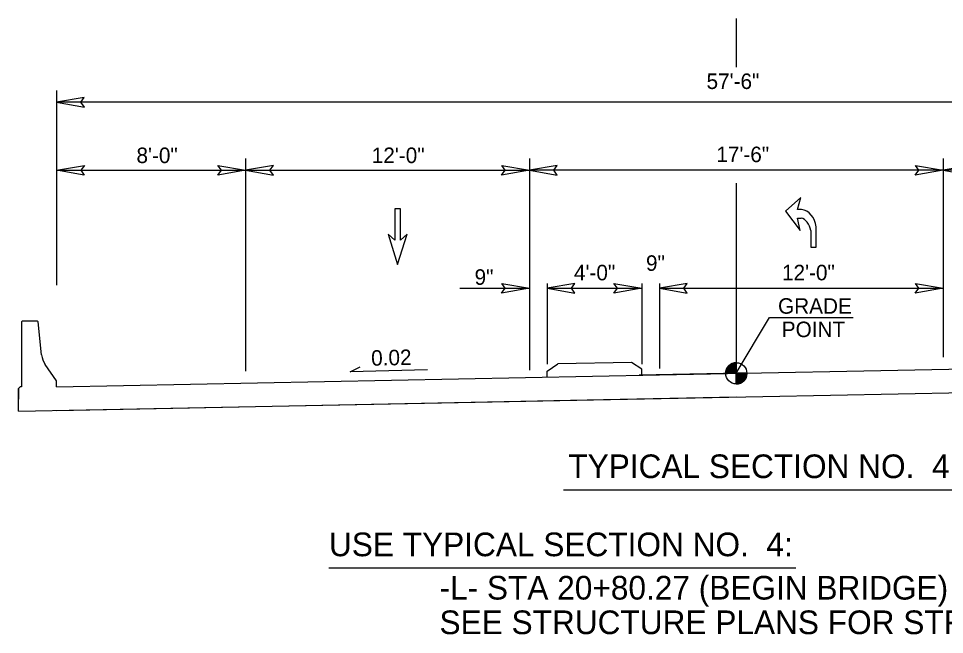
# Model space of a CAD drawing. Extents: x 1901582 to 1902252, y 193723 to 194156.
# Drawn here: x 1902016.27 to 1902055.44, y 193977.78 to 194003.82 of the extents above; entities that cross this region are included whole.
import ezdxf

# ---------------------------------------------------------------- set-up
doc = ezdxf.new("R2010")
doc.units = 0
for name, color, linetype in [('MARK BIKE LEFT ARROW CELL', 7, 'Continuous'), ('Old_Level_1', 7, 'Continuous'), ('Old_Level_11', 7, 'Continuous'), ('Old_Level_2', 7, 'Continuous'), ('Prop Dimension', 7, 'Continuous'), ('Prop Dimension Text', 7, 'Continuous'), ('Typical Grade Point Symbol CELL', 7, 'Continuous'), ('Typical Pavement Slope Information CELL', 7, 'Continuous'), ('Typical Terminator CELL', 7, 'Continuous'), ('Typical Text Grade Point CELL', 7, 'Continuous')]:
    doc.layers.add(name, color=color, linetype=linetype)

msp = doc.modelspace()

# ---------------------------------------------------------------- linework, layer by layer
at = {"layer": 'MARK BIKE LEFT ARROW CELL'}
for p, q in [((1902049.368, 193996.257), (1902048.718, 193995.672)), ((1902049.368, 193996.257), (1902048.718, 193995.672)), ((1902049.217, 193995.749), (1902049.368, 193996.257)), ((1902049.217, 193995.749), (1902049.368, 193996.257)), ((1902049.391, 193995.749), (1902049.217, 193995.749)), ((1902049.391, 193995.749), (1902049.217, 193995.749)), ((1902048.718, 193995.672), (1902049.333, 193994.864)), ((1902048.718, 193995.672), (1902049.333, 193994.864)), ((1902049.333, 193994.864), (1902049.217, 193995.383)), ((1902049.217, 193995.383), (1902049.372, 193995.383)), ((1902049.333, 193994.864), (1902049.217, 193995.383)), ((1902049.217, 193995.383), (1902049.372, 193995.383)), ((1902050.013, 193994.157), (1902050.013, 193995.018)), ((1902050.013, 193994.157), (1902050.013, 193995.018)), ((1902049.782, 193994.864), (1902049.782, 193994.157)), ((1902049.782, 193994.864), (1902049.782, 193994.157)), ((1902049.782, 193994.157), (1902050.013, 193994.157)), ((1902049.782, 193994.157), (1902050.013, 193994.157))]:
    msp.add_line(p, q, dxfattribs=at)
for centre, major_axis, ratio in [((1902049.455, 193995.082), (-0.294, 0.632), 0.75825), ((1902049.455, 193995.082), (-0.294, 0.632), 0.75825), ((1902049.436, 193994.928), (-0.204, 0.44), 0.652763), ((1902049.436, 193994.928), (-0.204, 0.44), 0.652763)]:
    msp.add_ellipse(centre, major_axis=major_axis, ratio=ratio, start_param=4.277405, end_param=5.848201, dxfattribs=at)
at = {"layer": 'Old_Level_1'}
for p, q in [((1902017.881, 194000.779), (1902017.881, 193992.543)), ((1902025.881, 193997.904), (1902025.881, 193988.912)), ((1902037.881, 193997.904), (1902037.881, 193988.95)), ((1902055.381, 193997.904), (1902055.381, 193989.501)), ((1902038.631, 193992.619), (1902038.631, 193989.203)), ((1902042.631, 193992.619), (1902042.631, 193989.203)), ((1902043.381, 193992.619), (1902043.381, 193989.025)), ((1902016.437, 193991.029), (1902016.404, 193990.996)), ((1902016.404, 193990.996), (1902016.404, 193988.248)), ((1902017.067, 193991.029), (1902016.437, 193991.029)), ((1902017.103, 193990.992), (1902017.067, 193991.029)), ((1902017.25, 193989.601), (1902017.103, 193990.992)), ((1902017.881, 193988.509), (1902017.402, 193989.194)), ((1902038.631, 193988.917), (1902039.089, 193989.218)), ((1902042.2, 193989.28), (1902039.089, 193989.218)), ((1902042.631, 193988.997), (1902042.2, 193989.28)), ((1902043.381, 193988.758), (1902075.381, 193989.398)), ((1902017.881, 193988.248), (1902043.381, 193988.758)), ((1902038.631, 193988.663), (1902038.631, 193988.917)), ((1902046.81, 193988.827), (1902042.523, 193988.741)), ((1902042.631, 193988.743), (1902042.631, 193988.997)), ((1902016.274, 193987.216), (1902076.989, 193988.43)), ((1902017.881, 193988.248), (1902017.881, 193988.509)), ((1902016.339, 193988.248), (1902016.274, 193988.183)), ((1902016.274, 193987.216), (1902016.274, 193988.183)), ((1902016.274, 193988.183), (1902016.274, 193987.726)), ((1902016.404, 193988.248), (1902016.339, 193988.248)), ((1902017.901, 193987.248), (1902046.631, 193987.823))]:
    msp.add_line(p, q, dxfattribs=at)
msp.add_arc((1902018.114, 193989.692), 0.869, 186.0111, 214.9913, dxfattribs=at)
at = {"layer": 'Old_Level_11'}
for p, q in [((1902046.631, 194003.817), (1902046.631, 194001.764)), ((1902046.631, 193996.855), (1902046.631, 193988.823)), ((1902039.318, 193983.898), (1902055.943, 193983.898)), ((1902029.404, 193980.597), (1902049.147, 193980.597))]:
    msp.add_line(p, q, dxfattribs=at)
at = {"layer": 'Prop Dimension'}
msp.add_lwpolyline([(1902032.705, 193994.696), (1902032.434, 193994.446), (1902032.434, 193995.779), (1902032.184, 193995.779), (1902032.184, 193994.446), (1902031.913, 193994.696), (1902032.309, 193993.425)], close=True, dxfattribs=at)
msp.add_lwpolyline([(1902032.705, 193994.696), (1902032.434, 193994.446), (1902032.434, 193995.779), (1902032.184, 193995.779), (1902032.184, 193994.446), (1902031.913, 193994.696), (1902032.309, 193993.425)], close=True, dxfattribs=at)
at = {"layer": 'Prop Dimension Text'}
for p, q in [((1902075.381, 194000.279), (1902017.881, 194000.279)), ((1902017.881, 193997.404), (1902025.881, 193997.404)), ((1902025.881, 193997.404), (1902037.881, 193997.404)), ((1902026.631, 193997.404), (1902037.631, 193997.404)), ((1902055.381, 193997.404), (1902037.881, 193997.404)), ((1902067.381, 193997.404), (1902055.381, 193997.404)), ((1902034.935, 193992.417), (1902037.881, 193992.417)), ((1902034.978, 193992.417), (1902037.881, 193992.417)), ((1902038.631, 193992.417), (1902042.631, 193992.417)), ((1902043.381, 193992.417), (1902055.381, 193992.417))]:
    msp.add_line(p, q, dxfattribs=at)
at = {"layer": 'Typical Grade Point Symbol CELL'}
for p, q in [((1902046.631, 193988.823), (1902046.631, 193989.271)), ((1902046.184, 193988.823), (1902046.631, 193988.823)), ((1902046.632, 193988.375), (1902046.631, 193988.823)), ((1902047.079, 193988.823), (1902046.631, 193988.823)), ((1902046.631, 193988.823), (1902046.632, 193988.375))]:
    msp.add_line(p, q, dxfattribs=at)
for points in [[(1902046.269, 193989.086), (1902046.269, 193988.823)], [(1902046.278, 193989.098), (1902046.278, 193988.823)], [(1902046.287, 193989.108), (1902046.287, 193988.823)], [(1902046.296, 193989.119), (1902046.296, 193988.823)], [(1902046.305, 193989.129), (1902046.305, 193988.823)], [(1902046.314, 193989.138), (1902046.314, 193988.823)], [(1902046.323, 193989.147), (1902046.323, 193988.823)], [(1902046.332, 193989.155), (1902046.332, 193988.823)], [(1902046.341, 193989.163), (1902046.341, 193988.823)], [(1902046.35, 193989.171), (1902046.35, 193988.823)], [(1902046.359, 193989.178), (1902046.359, 193988.823)], [(1902046.368, 193989.184), (1902046.368, 193988.823)], [(1902046.377, 193989.191), (1902046.377, 193988.823)], [(1902046.386, 193989.197), (1902046.386, 193988.823)], [(1902046.395, 193989.203), (1902046.395, 193988.823)], [(1902046.404, 193989.208), (1902046.404, 193988.823)], [(1902046.412, 193989.213), (1902046.412, 193988.823)], [(1902046.421, 193989.218), (1902046.421, 193988.823)], [(1902046.43, 193989.223), (1902046.43, 193988.823)], [(1902046.439, 193989.227), (1902046.439, 193988.823)], [(1902046.448, 193989.231), (1902046.448, 193988.823)], [(1902046.457, 193989.235), (1902046.457, 193988.823)], [(1902046.466, 193989.239), (1902046.466, 193988.823)], [(1902046.475, 193989.243), (1902046.475, 193988.823)], [(1902046.484, 193989.246), (1902046.484, 193988.823)], [(1902046.493, 193989.249), (1902046.493, 193988.823)], [(1902046.502, 193989.252), (1902046.502, 193988.823)], [(1902046.511, 193989.254), (1902046.511, 193988.823)], [(1902046.52, 193989.257), (1902046.52, 193988.823)], [(1902046.529, 193989.259), (1902046.529, 193988.823)], [(1902046.538, 193989.261), (1902046.538, 193988.823)], [(1902046.547, 193989.263), (1902046.547, 193988.823)], [(1902046.556, 193989.265), (1902046.556, 193988.823)], [(1902046.565, 193989.266), (1902046.565, 193988.823)], [(1902046.574, 193989.267), (1902046.574, 193988.823)], [(1902046.583, 193989.268), (1902046.583, 193988.823)], [(1902046.592, 193989.269), (1902046.592, 193988.823)], [(1902046.6, 193989.27), (1902046.6, 193988.823)], [(1902046.609, 193989.27), (1902046.609, 193988.823)], [(1902046.618, 193989.271), (1902046.618, 193988.823)], [(1902046.627, 193989.271), (1902046.627, 193989.271), (1902046.627, 193988.823)], [(1902046.189, 193988.887), (1902046.189, 193988.823)], [(1902046.198, 193988.932), (1902046.198, 193988.823)], [(1902046.207, 193988.963), (1902046.207, 193988.823)], [(1902046.216, 193988.988), (1902046.216, 193988.823)], [(1902046.224, 193989.009), (1902046.224, 193988.823)], [(1902046.233, 193989.028), (1902046.233, 193988.823)], [(1902046.242, 193989.044), (1902046.242, 193988.823)], [(1902046.251, 193989.059), (1902046.251, 193988.823)], [(1902046.26, 193989.073), (1902046.26, 193988.823)], [(1902046.638, 193988.823), (1902046.638, 193988.375), (1902046.638, 193988.375)], [(1902046.647, 193988.823), (1902046.647, 193988.375)], [(1902046.656, 193988.823), (1902046.656, 193988.376)], [(1902046.665, 193988.823), (1902046.665, 193988.376)], [(1902046.674, 193988.823), (1902046.674, 193988.377)], [(1902046.683, 193988.823), (1902046.683, 193988.378)], [(1902046.692, 193988.823), (1902046.692, 193988.379)], [(1902046.701, 193988.823), (1902046.701, 193988.381)], [(1902046.71, 193988.823), (1902046.71, 193988.382)], [(1902046.719, 193988.823), (1902046.719, 193988.384)], [(1902046.728, 193988.823), (1902046.728, 193988.386)], [(1902046.737, 193988.823), (1902046.737, 193988.388)], [(1902046.746, 193988.823), (1902046.746, 193988.39)], [(1902046.755, 193988.823), (1902046.755, 193988.393)], [(1902046.764, 193988.823), (1902046.764, 193988.395)], [(1902046.773, 193988.823), (1902046.773, 193988.398)], [(1902046.781, 193988.823), (1902046.781, 193988.401)], [(1902046.79, 193988.823), (1902046.79, 193988.404)], [(1902046.799, 193988.823), (1902046.799, 193988.408)], [(1902046.808, 193988.823), (1902046.808, 193988.412)], [(1902046.817, 193988.823), (1902046.817, 193988.416)], [(1902046.826, 193988.823), (1902046.826, 193988.42)], [(1902046.835, 193988.823), (1902046.835, 193988.424)], [(1902046.844, 193988.823), (1902046.844, 193988.429)], [(1902046.853, 193988.823), (1902046.853, 193988.434)], [(1902046.862, 193988.823), (1902046.862, 193988.439)], [(1902046.871, 193988.823), (1902046.871, 193988.445)], [(1902046.88, 193988.823), (1902046.88, 193988.451)], [(1902046.889, 193988.823), (1902046.889, 193988.457)], [(1902046.898, 193988.823), (1902046.898, 193988.463)], [(1902046.907, 193988.823), (1902046.907, 193988.47)], [(1902046.916, 193988.823), (1902046.916, 193988.477)], [(1902046.925, 193988.823), (1902046.925, 193988.485)], [(1902046.934, 193988.823), (1902046.934, 193988.493)], [(1902046.943, 193988.823), (1902046.943, 193988.501)], [(1902046.952, 193988.823), (1902046.952, 193988.51)], [(1902046.961, 193988.823), (1902046.961, 193988.52)], [(1902046.969, 193988.823), (1902046.969, 193988.53)], [(1902046.978, 193988.823), (1902046.978, 193988.541)], [(1902046.987, 193988.823), (1902046.987, 193988.551)], [(1902046.996, 193988.823), (1902046.996, 193988.563)], [(1902047.005, 193988.823), (1902047.005, 193988.576)], [(1902047.014, 193988.823), (1902047.014, 193988.59)], [(1902047.023, 193988.823), (1902047.023, 193988.606)], [(1902047.032, 193988.823), (1902047.032, 193988.623)], [(1902047.041, 193988.823), (1902047.041, 193988.642)], [(1902047.05, 193988.823), (1902047.05, 193988.663)], [(1902047.059, 193988.823), (1902047.059, 193988.69)], [(1902047.068, 193988.823), (1902047.068, 193988.722)], [(1902047.077, 193988.823), (1902047.077, 193988.774)]]:
    msp.add_lwpolyline(points, dxfattribs=at)
msp.add_circle((1902046.632, 193988.823), 0.448, dxfattribs=at)
for start, end in [(90.0095, 180.0095), (270.0095, 0.0095)]:
    msp.add_arc((1902046.632, 193988.823), 0.448, start, end, dxfattribs=at)
at = {"layer": 'Typical Pavement Slope Information CELL'}
for p, q in [((1902030.296, 193988.882), (1902030.717, 193989.095)), ((1902033.57, 193988.962), (1902030.296, 193988.882))]:
    msp.add_line(p, q, dxfattribs=at)
at = {"layer": 'Typical Terminator CELL'}
for points in [[(1902019.053, 194000.481), (1902017.881, 194000.279), (1902019.059, 194000.071), (1902018.91, 194000.279)], [(1902019.053, 193997.202), (1902017.881, 193997.404), (1902019.059, 193997.612), (1902018.91, 193997.404)], [(1902024.71, 193997.606), (1902025.881, 193997.404), (1902024.703, 193997.196), (1902024.853, 193997.404)], [(1902027.053, 193997.606), (1902025.881, 193997.404), (1902027.059, 193997.196), (1902026.91, 193997.404)], [(1902036.71, 193997.606), (1902037.881, 193997.404), (1902036.703, 193997.196), (1902036.853, 193997.404)], [(1902039.053, 193997.606), (1902037.881, 193997.404), (1902039.059, 193997.196), (1902038.91, 193997.404)], [(1902054.21, 193997.606), (1902055.381, 193997.404), (1902054.203, 193997.196), (1902054.353, 193997.404)], [(1902056.553, 193997.606), (1902055.381, 193997.404), (1902056.559, 193997.196), (1902056.41, 193997.404)], [(1902036.71, 193992.619), (1902037.881, 193992.417), (1902036.703, 193992.209), (1902036.853, 193992.417)], [(1902039.803, 193992.619), (1902038.631, 193992.417), (1902039.809, 193992.209), (1902039.66, 193992.417)], [(1902041.46, 193992.619), (1902042.631, 193992.417), (1902041.453, 193992.209), (1902041.603, 193992.417)], [(1902044.553, 193992.619), (1902043.381, 193992.417), (1902044.559, 193992.209), (1902044.41, 193992.417)], [(1902054.21, 193992.619), (1902055.381, 193992.417), (1902054.203, 193992.209), (1902054.353, 193992.417)]]:
    msp.add_lwpolyline(points, close=True, dxfattribs=at)
at = {"layer": 'Typical Text Grade Point CELL'}
for p, q in [((1902046.631, 193988.823), (1902048.035, 193991.183)), ((1902048.035, 193991.183), (1902051.573, 193991.183))]:
    msp.add_line(p, q, dxfattribs=at)

# ---------------------------------------------------------------- texts
at = {"layer": 'Old_Level_1'}
for p in [(1902042.813, 193993.152), (1902035.563, 193992.562)]:
    msp.add_text('9"', height=0.656, dxfattribs=at).set_placement(p)
at = {"layer": 'Old_Level_11'}
for s, p in [('TYPICAL SECTION NO.  4', (1902039.528, 193984.392)), ('USE TYPICAL SECTION NO.  4:', (1902029.404, 193981.091)), ('-L- STA 20+80.27 (BEGIN BRIDGE) TO 23+18.27 (END BRIDGE)', (1902034.08, 193979.259)), ('SEE STRUCTURE PLANS FOR STRUCTURE CONSTRUCTION DETAILS', (1902034.08, 193977.798))]:
    msp.add_text(s, height=1, dxfattribs=at).set_placement(p)
at = {"layer": 'Old_Level_2'}
msp.add_text('0.02', height=0.656, rotation=1.1916, dxfattribs=at).set_placement((1902031.196, 193989.14))
at = {"layer": 'Prop Dimension Text'}
for s, p in [('57\'-6"', (1902045.375, 194000.838)), ('8\'-0"', (1902021.263, 193997.707)), ('12\'-0"', (1902031.215, 193997.708)), ('17\'-6"', (1902045.789, 193997.747)), ('4\'-0"', (1902039.766, 193992.752)), ('12\'-0"', (1902048.566, 193992.752))]:
    msp.add_text(s, height=0.656, dxfattribs=at).set_placement(p)
at = {"layer": 'Typical Text Grade Point CELL'}
for s, p in [('GRADE', (1902048.399, 193991.34)), ('POINT', (1902048.556, 193990.351))]:
    msp.add_text(s, height=0.656, dxfattribs=at).set_placement(p)

doc.saveas('drawing.dxf')
